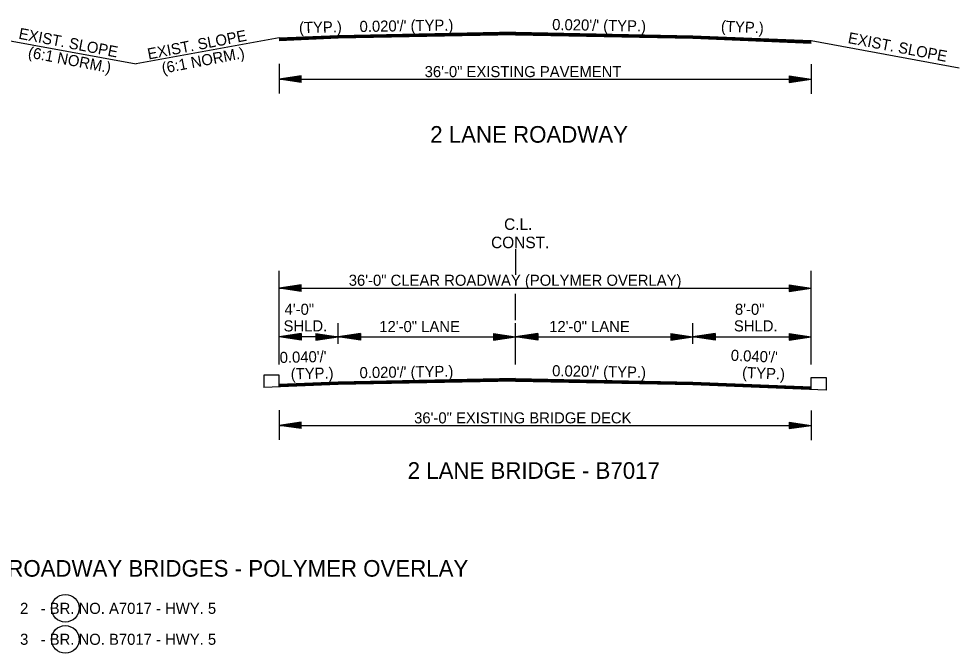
# Model space of a CAD drawing. Extents: x 544199 to 1930787, y -1968972 to 596640.
# Drawn here: x 546713 to 547350, y -1948308 to -1947878 of the extents above; entities that cross this region are included whole.
import ezdxf

# ---------------------------------------------------------------- set-up
doc = ezdxf.new("R2010")
doc.units = 0
doc.layers.add('R_Border', color=7, linetype='Continuous')
doc.layers.add('R_Draft', color=7, linetype='Continuous')

msp = doc.modelspace()

# ---------------------------------------------------------------- linework, layer by layer
at = {"layer": 'R_Border'}
for p, q in [((546929.49, -1947889.93), (546889.49, -1947891.53)), ((547169.49, -1947889.93), (547249.49, -1947893.13)), ((546929.49, -1947890.23), (546889.49, -1947891.83)), ((546929.49, -1947890.53), (546889.49, -1947892.13)), ((546929.49, -1947890.83), (546889.49, -1947892.43)), ((546929.49, -1947891.13), (546889.49, -1947892.73)), ((546929.49, -1947891.43), (546889.49, -1947893.03)), ((546929.49, -1947891.6), (546889.49, -1947893.2)), ((547169.49, -1947890.23), (547249.49, -1947893.43)), ((547169.49, -1947890.53), (547249.49, -1947893.73)), ((547169.49, -1947890.83), (547249.49, -1947894.03)), ((547169.49, -1947891.13), (547249.49, -1947894.33)), ((547169.49, -1947891.43), (547249.49, -1947894.63)), ((547169.49, -1947891.6), (547249.49, -1947894.8)), ((546879.31, -1948119.5), (546879.3, -1948127.99)), ((546889.48, -1948119.5), (546879.31, -1948119.5)), ((546889.48, -1948127.41), (546889.48, -1948119.5)), ((546929.48, -1948124.31), (546889.48, -1948125.91)), ((546929.48, -1948124.61), (546889.48, -1948126.21)), ((546929.48, -1948124.91), (546889.48, -1948126.51)), ((546929.48, -1948125.21), (546889.48, -1948126.81)), ((547169.48, -1948124.31), (547249.48, -1948127.51)), ((547169.48, -1948124.61), (547249.48, -1948127.81)), ((547169.48, -1948124.91), (547249.48, -1948128.11)), ((547169.48, -1948125.21), (547249.48, -1948128.41)), ((547249.48, -1948121.1), (547259.64, -1948121.1)), ((547249.48, -1948129.01), (547249.48, -1948121.1)), ((547259.64, -1948121.1), (547259.65, -1948129.72)), ((546929.48, -1948125.98), (546879.3, -1948127.99)), ((546929.48, -1948125.51), (546889.48, -1948127.11)), ((546929.48, -1948125.81), (546889.48, -1948127.41)), ((547169.48, -1948125.51), (547249.48, -1948128.71)), ((547169.48, -1948125.81), (547249.48, -1948129.01)), ((547169.48, -1948125.98), (547259.65, -1948129.59))]:
    msp.add_line(p, q, dxfattribs=at)
for centre in [(546744.9, -1948277.38), (546744.9, -1948298.48)]:
    msp.add_circle(centre, 9.34, dxfattribs=at)
at = {"layer": 'R_Draft'}
for p, q in [((547049.49, -1947887.53), (546929.49, -1947889.93)), ((547049.49, -1947887.83), (546929.49, -1947890.23)), ((547049.49, -1947888.13), (546929.49, -1947890.53)), ((547049.49, -1947888.43), (546929.49, -1947890.83)), ((547049.49, -1947888.73), (546929.49, -1947891.13)), ((547049.49, -1947889.03), (546929.49, -1947891.43)), ((547049.49, -1947889.2), (546929.49, -1947891.6)), ((547049.49, -1947887.53), (547169.49, -1947889.93)), ((547049.49, -1947887.83), (547169.49, -1947890.23)), ((547049.49, -1947888.13), (547169.49, -1947890.53)), ((547049.49, -1947888.43), (547169.49, -1947890.83)), ((547049.49, -1947888.73), (547169.49, -1947891.13)), ((547049.49, -1947889.03), (547169.49, -1947891.43)), ((547049.49, -1947889.2), (547169.49, -1947891.6)), ((546698.19, -1947891.53), (546792.89, -1947908.93)), ((546889.49, -1947891.19), (546792.89, -1947908.93)), ((547249.49, -1947893.13), (547349.56, -1947911.51)), ((546889.49, -1947908.94), (546889.49, -1947928.94)), ((547249.49, -1947909.19), (547249.49, -1947929.19)), ((546904.49, -1947916.94), (546889.49, -1947919.19)), ((546904.49, -1947921.44), (546889.49, -1947919.19)), ((546889.49, -1947919.19), (547239.49, -1947919.19)), ((546904.49, -1947917.32), (546891.99, -1947919.19)), ((546904.49, -1947921.07), (546891.99, -1947919.19)), ((546904.49, -1947917.7), (546894.57, -1947919.19)), ((546904.49, -1947920.69), (546894.57, -1947919.19)), ((546904.49, -1947918.08), (546897.07, -1947919.19)), ((546904.49, -1947920.31), (546897.07, -1947919.19)), ((546904.49, -1947918.46), (546899.61, -1947919.19)), ((546904.49, -1947919.92), (546899.61, -1947919.19)), ((546904.49, -1947918.84), (546902.12, -1947919.19)), ((546904.49, -1947919.55), (546902.12, -1947919.19)), ((546904.49, -1947921.44), (546904.49, -1947916.94)), ((547234.49, -1947916.94), (547249.49, -1947919.19)), ((547234.49, -1947916.94), (547234.49, -1947921.44)), ((547234.49, -1947917.32), (547246.98, -1947919.19)), ((547234.49, -1947917.7), (547244.4, -1947919.19)), ((547234.49, -1947918.08), (547241.9, -1947919.19)), ((547234.49, -1947918.47), (547239.36, -1947919.19)), ((547234.49, -1947918.84), (547236.86, -1947919.19)), ((547234.49, -1947921.44), (547249.49, -1947919.19)), ((547234.49, -1947919.93), (547239.36, -1947919.19)), ((547234.49, -1947920.69), (547244.4, -1947919.19)), ((547234.49, -1947921.07), (547246.98, -1947919.19)), ((547234.49, -1947920.31), (547241.9, -1947919.19)), ((547234.49, -1947919.55), (547236.86, -1947919.19)), ((547049.63, -1948051.66), (547049.63, -1948034.33)), ((546889.48, -1948112.36), (546889.48, -1948048.95)), ((547249.48, -1948112.36), (547249.48, -1948048.95)), ((546904.48, -1948058.52), (546889.48, -1948060.77)), ((546889.48, -1948060.77), (547239.48, -1948060.77)), ((546904.48, -1948063.02), (546889.48, -1948060.77)), ((546904.48, -1948058.89), (546891.98, -1948060.77)), ((546904.48, -1948062.64), (546891.98, -1948060.77)), ((546904.48, -1948059.27), (546894.56, -1948060.77)), ((546904.48, -1948062.26), (546894.56, -1948060.77)), ((546904.48, -1948059.65), (546897.06, -1948060.77)), ((546904.48, -1948061.88), (546897.06, -1948060.77)), ((546904.48, -1948060.03), (546899.6, -1948060.77)), ((546904.48, -1948061.49), (546899.6, -1948060.77)), ((546904.48, -1948060.41), (546902.11, -1948060.77)), ((546904.48, -1948061.12), (546902.11, -1948060.77)), ((546904.48, -1948063.02), (546904.48, -1948058.52)), ((547234.48, -1948058.52), (547249.48, -1948060.77)), ((547234.48, -1948058.52), (547234.48, -1948063.02)), ((547234.48, -1948058.89), (547246.97, -1948060.77)), ((547234.48, -1948059.27), (547244.39, -1948060.77)), ((547234.48, -1948059.65), (547241.89, -1948060.77)), ((547234.48, -1948060.04), (547239.35, -1948060.77)), ((547234.48, -1948060.41), (547236.85, -1948060.77)), ((547234.48, -1948063.02), (547249.48, -1948060.77)), ((547234.48, -1948061.5), (547239.35, -1948060.77)), ((547234.48, -1948062.26), (547244.39, -1948060.77)), ((547234.48, -1948062.64), (547246.97, -1948060.77)), ((547234.48, -1948061.88), (547241.89, -1948060.77)), ((547234.48, -1948061.12), (547236.85, -1948060.77)), ((547049.48, -1948074.3), (547049.48, -1948064.49)), ((547049.48, -1948082.29), (547049.48, -1948074.3)), ((546929.48, -1948098.39), (546929.48, -1948084.41)), ((547049.48, -1948112.36), (547049.48, -1948084.41)), ((547169.48, -1948098.39), (547169.48, -1948084.41)), ((546904.48, -1948091.35), (546889.48, -1948093.6)), ((546904.48, -1948091.73), (546891.98, -1948093.6)), ((546904.48, -1948092.11), (546894.56, -1948093.6)), ((546904.48, -1948092.48), (546897.06, -1948093.6)), ((546904.48, -1948092.87), (546899.6, -1948093.6)), ((546904.48, -1948093.25), (546902.11, -1948093.6)), ((546904.48, -1948091.35), (546904.48, -1948095.85)), ((546914.48, -1948091.35), (546929.48, -1948093.6)), ((546914.48, -1948091.35), (546914.48, -1948095.85)), ((546914.48, -1948091.73), (546926.97, -1948093.6)), ((546914.48, -1948092.11), (546924.39, -1948093.6)), ((546914.48, -1948092.48), (546921.89, -1948093.6)), ((546914.48, -1948092.87), (546919.35, -1948093.6)), ((546914.48, -1948093.25), (546916.85, -1948093.6)), ((546944.48, -1948091.35), (546929.48, -1948093.6)), ((546944.48, -1948091.73), (546931.98, -1948093.6)), ((546944.48, -1948092.11), (546934.56, -1948093.6)), ((546944.48, -1948092.48), (546937.06, -1948093.6)), ((546944.48, -1948092.87), (546939.6, -1948093.6)), ((546944.48, -1948093.25), (546942.11, -1948093.6)), ((546944.48, -1948091.35), (546944.48, -1948095.85)), ((547034.48, -1948091.35), (547049.48, -1948093.6)), ((547034.48, -1948091.35), (547034.48, -1948095.85)), ((547034.48, -1948091.73), (547046.97, -1948093.6)), ((547034.48, -1948092.11), (547044.39, -1948093.6)), ((547034.48, -1948092.48), (547041.89, -1948093.6)), ((547034.48, -1948092.87), (547039.35, -1948093.6)), ((547034.48, -1948093.25), (547036.85, -1948093.6)), ((547064.48, -1948091.35), (547049.48, -1948093.6)), ((547064.48, -1948091.73), (547051.98, -1948093.6)), ((547064.48, -1948092.11), (547054.56, -1948093.6)), ((547064.48, -1948092.48), (547057.06, -1948093.6)), ((547064.48, -1948092.87), (547059.6, -1948093.6)), ((547064.48, -1948093.25), (547062.11, -1948093.6)), ((547064.48, -1948091.35), (547064.48, -1948095.85)), ((547154.48, -1948091.35), (547169.48, -1948093.6)), ((547154.48, -1948091.35), (547154.48, -1948095.85)), ((547154.48, -1948091.73), (547166.97, -1948093.6)), ((547154.48, -1948092.11), (547164.39, -1948093.6)), ((547154.48, -1948092.48), (547161.89, -1948093.6)), ((547154.48, -1948092.87), (547159.35, -1948093.6)), ((547154.48, -1948093.25), (547156.85, -1948093.6)), ((547184.48, -1948091.35), (547169.48, -1948093.6)), ((547184.48, -1948091.73), (547171.98, -1948093.6)), ((547184.48, -1948092.11), (547174.56, -1948093.6)), ((547184.48, -1948092.48), (547177.06, -1948093.6)), ((547184.48, -1948092.87), (547179.6, -1948093.6)), ((547184.48, -1948093.25), (547182.11, -1948093.6)), ((547184.48, -1948091.35), (547184.48, -1948095.85)), ((547234.48, -1948091.35), (547249.48, -1948093.6)), ((547234.48, -1948091.35), (547234.48, -1948095.85)), ((547234.48, -1948091.73), (547246.97, -1948093.6)), ((547234.48, -1948092.11), (547244.39, -1948093.6)), ((547234.48, -1948092.48), (547241.89, -1948093.6)), ((547234.48, -1948092.87), (547239.35, -1948093.6)), ((547234.48, -1948093.25), (547236.85, -1948093.6)), ((546929.48, -1948093.6), (546889.48, -1948093.6)), ((546904.48, -1948095.85), (546889.48, -1948093.6)), ((546904.48, -1948095.48), (546891.98, -1948093.6)), ((546904.48, -1948095.09), (546894.56, -1948093.6)), ((546904.48, -1948094.72), (546897.06, -1948093.6)), ((546904.48, -1948094.34), (546899.6, -1948093.6)), ((546904.48, -1948093.95), (546902.11, -1948093.6)), ((546914.48, -1948095.85), (546929.48, -1948093.6)), ((546914.48, -1948094.34), (546919.35, -1948093.6)), ((546914.48, -1948095.09), (546924.39, -1948093.6)), ((546914.48, -1948095.48), (546926.97, -1948093.6)), ((546914.48, -1948094.72), (546921.89, -1948093.6)), ((546914.48, -1948093.95), (546916.85, -1948093.6)), ((546929.48, -1948093.6), (547049.48, -1948093.6)), ((546944.48, -1948095.85), (546929.48, -1948093.6)), ((546944.48, -1948095.48), (546931.98, -1948093.6)), ((546944.48, -1948095.09), (546934.56, -1948093.6)), ((546944.48, -1948094.72), (546937.06, -1948093.6)), ((546944.48, -1948094.34), (546939.6, -1948093.6)), ((546944.48, -1948093.95), (546942.11, -1948093.6)), ((547034.48, -1948095.85), (547049.48, -1948093.6)), ((547034.48, -1948094.34), (547039.35, -1948093.6)), ((547034.48, -1948095.09), (547044.39, -1948093.6)), ((547034.48, -1948095.48), (547046.97, -1948093.6)), ((547034.48, -1948094.72), (547041.89, -1948093.6)), ((547034.48, -1948093.95), (547036.85, -1948093.6)), ((547049.48, -1948093.6), (547169.48, -1948093.6)), ((547064.48, -1948095.85), (547049.48, -1948093.6)), ((547064.48, -1948095.48), (547051.98, -1948093.6)), ((547064.48, -1948095.09), (547054.56, -1948093.6)), ((547064.48, -1948094.72), (547057.06, -1948093.6)), ((547064.48, -1948094.34), (547059.6, -1948093.6)), ((547064.48, -1948093.95), (547062.11, -1948093.6)), ((547154.48, -1948095.85), (547169.48, -1948093.6)), ((547154.48, -1948094.34), (547159.35, -1948093.6)), ((547154.48, -1948095.09), (547164.39, -1948093.6)), ((547154.48, -1948095.48), (547166.97, -1948093.6)), ((547154.48, -1948094.72), (547161.89, -1948093.6)), ((547154.48, -1948093.95), (547156.85, -1948093.6)), ((547169.48, -1948093.6), (547239.48, -1948093.6)), ((547184.48, -1948095.85), (547169.48, -1948093.6)), ((547184.48, -1948095.48), (547171.98, -1948093.6)), ((547184.48, -1948095.09), (547174.56, -1948093.6)), ((547184.48, -1948094.72), (547177.06, -1948093.6)), ((547184.48, -1948094.34), (547179.6, -1948093.6)), ((547184.48, -1948093.95), (547182.11, -1948093.6)), ((547234.48, -1948095.85), (547249.48, -1948093.6)), ((547234.48, -1948094.34), (547239.35, -1948093.6)), ((547234.48, -1948095.09), (547244.39, -1948093.6)), ((547234.48, -1948095.48), (547246.97, -1948093.6)), ((547234.48, -1948094.72), (547241.89, -1948093.6)), ((547234.48, -1948093.95), (547236.85, -1948093.6)), ((547049.48, -1948121.91), (546929.48, -1948124.31)), ((547049.48, -1948122.21), (546929.48, -1948124.61)), ((547049.48, -1948122.51), (546929.48, -1948124.91)), ((547049.48, -1948122.81), (546929.48, -1948125.21)), ((547049.48, -1948123.11), (546929.48, -1948125.51)), ((547049.48, -1948123.41), (546929.48, -1948125.81)), ((547049.48, -1948123.58), (546929.48, -1948125.98)), ((547049.48, -1948121.91), (547169.48, -1948124.31)), ((547049.48, -1948122.21), (547169.48, -1948124.61)), ((547049.48, -1948122.51), (547169.48, -1948124.91)), ((547049.48, -1948122.81), (547169.48, -1948125.21)), ((547049.48, -1948123.11), (547169.48, -1948125.51)), ((547049.48, -1948123.41), (547169.48, -1948125.81)), ((547049.48, -1948123.58), (547169.48, -1948125.98)), ((546889.48, -1948143.32), (546889.48, -1948163.32)), ((547249.48, -1948143.57), (547249.48, -1948163.57)), ((546904.48, -1948151.32), (546889.48, -1948153.57)), ((546904.48, -1948155.82), (546889.48, -1948153.57)), ((546889.48, -1948153.57), (547239.48, -1948153.57)), ((546904.48, -1948151.69), (546891.98, -1948153.57)), ((546904.48, -1948155.44), (546891.98, -1948153.57)), ((546904.48, -1948152.08), (546894.56, -1948153.57)), ((546904.48, -1948155.06), (546894.56, -1948153.57)), ((546904.48, -1948152.45), (546897.06, -1948153.57)), ((546904.48, -1948154.69), (546897.06, -1948153.57)), ((546904.48, -1948152.83), (546899.6, -1948153.57)), ((546904.48, -1948154.3), (546899.6, -1948153.57)), ((546904.48, -1948153.22), (546902.11, -1948153.57)), ((546904.48, -1948153.92), (546902.11, -1948153.57)), ((546904.48, -1948155.82), (546904.48, -1948151.32)), ((547234.48, -1948151.32), (547249.48, -1948153.57)), ((547234.48, -1948151.32), (547234.48, -1948155.82)), ((547234.48, -1948151.69), (547246.97, -1948153.57)), ((547234.48, -1948152.08), (547244.39, -1948153.57)), ((547234.48, -1948152.45), (547241.89, -1948153.57)), ((547234.48, -1948152.84), (547239.35, -1948153.57)), ((547234.48, -1948153.22), (547236.85, -1948153.57)), ((547234.48, -1948155.82), (547249.48, -1948153.57)), ((547234.48, -1948154.3), (547239.35, -1948153.57)), ((547234.48, -1948155.06), (547244.39, -1948153.57)), ((547234.48, -1948155.44), (547246.97, -1948153.57)), ((547234.48, -1948154.69), (547241.89, -1948153.57)), ((547234.48, -1948153.92), (547236.85, -1948153.57))]:
    msp.add_line(p, q, dxfattribs=at)

# ---------------------------------------------------------------- texts
for s, rotation, p in [('(TYP.)', 1.31838, (546903.06, -1947888.09)), ("0.020'/' (TYP.)", 0.97192, (546944.01, -1947887.33)), ("0.020'/' (TYP.)", 359.02808, (547074.19, -1947885.96)), (' (TYP.)', 357.55203, (547185.49, -1947886.93)), ('EXIST. SLOPE ', 349.11714, (546712.92, -1947891.79)), ('EXIST. SLOPE', 10.88286, (546801.24, -1947905.99)), ('EXIST. SLOPE', 349.11714, (547273.87, -1947894.73)), ('(6:1 NORM.)', 349.11714, (546719.26, -1947904.46)), (' (6:1 NORM.)', 10.88286, (546808.14, -1947916.11)), ("0.040'/'", 1.31838, (546890, -1948111.38)), ("  0.040'/'", 357.55203, (547189.36, -1948109.59)), ('(TYP.)', 1.31838, (546897.46, -1948122.46)), ("0.020'/' (TYP.)", 0.97192, (546944, -1948121.7)), ("0.020'/' (TYP.)", 359.02808, (547074.18, -1948120.33)), (' (TYP.)', 357.55203, (547199.83, -1948121.3))]:
    msp.add_text(s, height=7.5, rotation=rotation, dxfattribs=at).set_placement(p)
for s, height, p in [('36\'-0" EXISTING PAVEMENT', 7.5, (546987.98, -1947917.87)), ('2 LANE ROADWAY', 11.25, (546991.76, -1947962.24)), ('C.L.', 7.8, (547041.71, -1948021.29)), ('CONST.', 7.8, (547032.93, -1948033.66)), ('36\'-0" CLEAR ROADWAY (POLYMER OVERLAY)', 7.5, (546936.62, -1948059.1)), ('4\'-0"', 7.5, (546893.23, -1948078.74)), ('8\'-0"', 7.5, (547197.86, -1948078.74)), ('SHLD.', 7.5, (546892.55, -1948089.99)), ('12\'-0" LANE', 7.5, (546957.29, -1948090.43)), ('12\'-0" LANE', 7.5, (547072.21, -1948090.43)), ('SHLD.', 7.5, (547197.18, -1948089.99)), ('36\'-0" EXISTING BRIDGE DECK', 7.5, (546980.85, -1948152.25)), ('2 LANE BRIDGE - B7017', 11.25, (546976.51, -1948189.78)), ('36 FT. CLEAR ROADWAY BRIDGES - POLYMER OVERLAY', 11.25, (546603.69, -1948256.01)), ('      2   - BR. NO. A7017 - HWY. 5', 7.5, (546697.58, -1948281.19)), ('      3   - BR. NO. B7017 - HWY. 5', 7.5, (546697.58, -1948302.14))]:
    msp.add_text(s, height=height, dxfattribs=at).set_placement(p)

doc.saveas('drawing.dxf')
